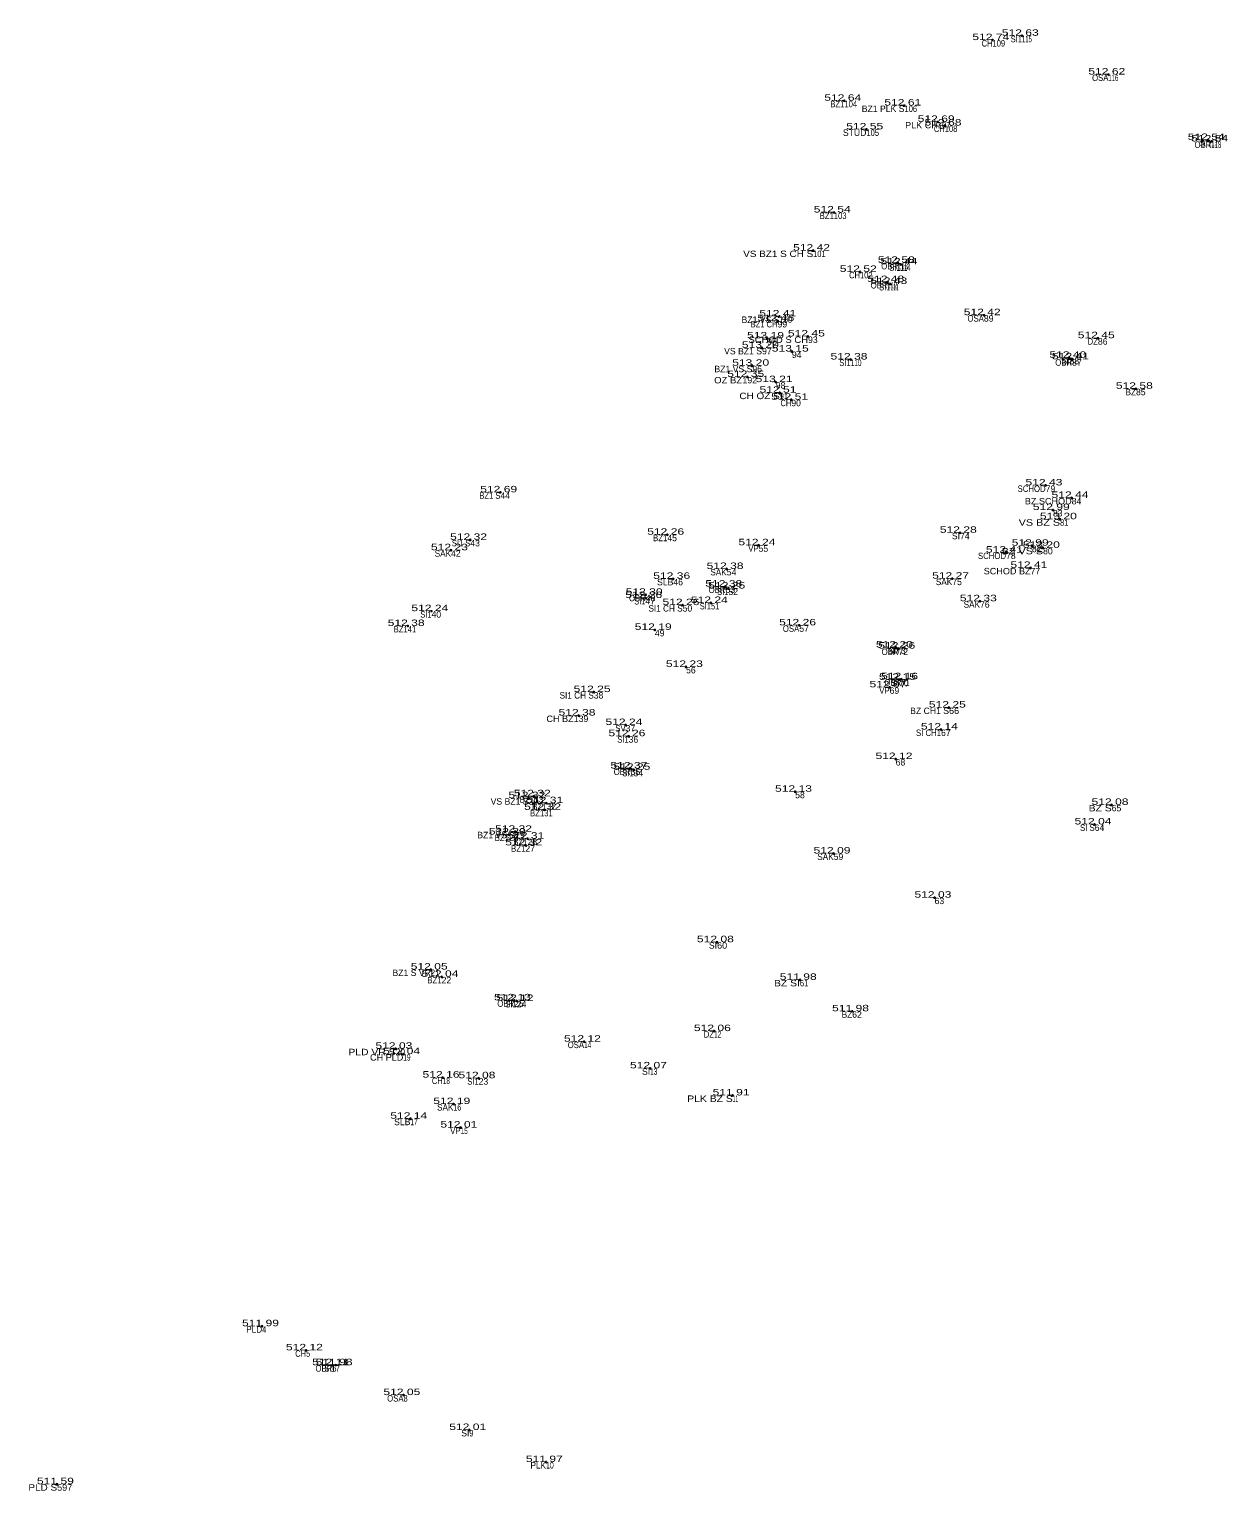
# Model space of a CAD drawing. Extents: x -643086 to -639283, y -1131805 to -1123269.
# Drawn here: x -639339.2 to -639283.5, y -1123337.4 to -1123269.5 of the extents above; entities that cross this region are included whole.
import ezdxf
from ezdxf.enums import TextEntityAlignment as Align

# ---------------------------------------------------------------- set-up
doc = ezdxf.new("R2010")
doc.units = 0
doc.header["$LTSCALE"] = 0.12
doc.header["$PDMODE"] = 32
doc.header["$PDSIZE"] = 0.06
for name, color, linetype in [('1', 7, 'Continuous'), ('2', 7, 'Continuous'), ('3', 7, 'Continuous'), ('4', 7, 'Continuous')]:
    doc.layers.add(name, color=color, linetype=linetype)

msp = doc.modelspace()

# ---------------------------------------------------------------- linework, layer by layer
at = {"layer": '1'}
for p in [(-639294.4, -1123269.99), (-639293.03, -1123269.79), (-639289.01, -1123271.59), (-639301.28, -1123272.81), (-639298.49, -1123273.03), (-639296.94, -1123273.79), (-639300.26, -1123274.14), (-639296.62, -1123273.96), (-639284.39, -1123274.63), (-639284.23, -1123274.7), (-639301.77, -1123278), (-639302.73, -1123279.77), (-639298.79, -1123280.34), (-639298.67, -1123280.41), (-639300.56, -1123280.76), (-639299.28, -1123281.23), (-639299.14, -1123281.32), (-639304.39, -1123283.04), (-639304.3, -1123282.83), (-639294.8, -1123282.77), (-639304.87, -1123283.85), (-639302.97, -1123283.76), (-639289.5, -1123283.84), (-639305.11, -1123284.29), (-639303.72, -1123284.46), (-639305.56, -1123285.12), (-639300.99, -1123284.83), (-639290.82, -1123284.75), (-639290.7, -1123284.82), (-639305.79, -1123285.64), (-639304.47, -1123285.88), (-639304.29, -1123286.37), (-639303.75, -1123286.7), (-639287.73, -1123286.19), (-639291.93, -1123290.68), (-639317.27, -1123291), (-639290.72, -1123291.26), (-639291.59, -1123291.82), (-639291.26, -1123292.25), (-639318.67, -1123293.21), (-639309.51, -1123292.97), (-639305.27, -1123293.46), (-639295.91, -1123292.88), (-639292.57, -1123293.48), (-639319.56, -1123293.69), (-639293.77, -1123293.8), (-639292.05, -1123293.58), (-639306.75, -1123294.56), (-639292.63, -1123294.51), (-639309.23, -1123295.02), (-639306.81, -1123295.38), (-639306.67, -1123295.47), (-639296.27, -1123295.01), (-639310.53, -1123295.91), (-639310.51, -1123295.76), (-639308.8, -1123296.24), (-639307.48, -1123296.14), (-639294.98, -1123296.06), (-639320.47, -1123296.52), (-639321.57, -1123297.21), (-639310.09, -1123297.39), (-639303.38, -1123297.18), (-639298.88, -1123298.21), (-639298.77, -1123298.26), (-639308.64, -1123299.11), (-639312.93, -1123300.28), (-639299.18, -1123300.06), (-639298.74, -1123299.71), (-639298.64, -1123299.68), (-639313.63, -1123301.37), (-639296.42, -1123301), (-639311.45, -1123301.81), (-639311.31, -1123302.33), (-639296.79, -1123302.02), (-639298.9, -1123303.39), (-639311.22, -1123303.83), (-639311.08, -1123303.89), (-639303.57, -1123304.91), (-639315.96, -1123305.21), (-639315.71, -1123305.12), (-639315.13, -1123305.44), (-639288.86, -1123305.52), (-639315.23, -1123305.75), (-639316.87, -1123306.9), (-639316.58, -1123306.77), (-639316.01, -1123307.09), (-639289.65, -1123306.43), (-639316.11, -1123307.4), (-639301.78, -1123307.78), (-639297.09, -1123309.83), (-639307.2, -1123311.9), (-639320.5, -1123313.17), (-639320, -1123313.51), (-639303.35, -1123313.65), (-639316.63, -1123314.6), (-639316.51, -1123314.63), (-639300.92, -1123315.11), (-639313.38, -1123316.52), (-639307.34, -1123316.03), (-639322.14, -1123316.85), (-639321.78, -1123317.1), (-639310.31, -1123317.76), (-639319.95, -1123318.19), (-639318.28, -1123318.22), (-639306.47, -1123319.02), (-639319.45, -1123319.42), (-639321.45, -1123320.1), (-639319.12, -1123320.51), (-639328.34, -1123329.74), (-639326.3, -1123330.86), (-639325.08, -1123331.55), (-639324.92, -1123331.55), (-639321.77, -1123332.94), (-639318.71, -1123334.56), (-639315.15, -1123336.05), (-639337.87, -1123337.08)]:
    msp.add_point(p, dxfattribs=at)

# ---------------------------------------------------------------- texts
at = {"layer": '2'}
for s, width, p in [('109', 0.85, (-639294.4, -1123270.29)), ('115', 0.55, (-639293.03, -1123270.09)), ('116', 0.55, (-639289.01, -1123271.89)), ('104', 0.85, (-639301.28, -1123273.11)), ('106', 0.85, (-639298.49, -1123273.33)), ('107', 0.85, (-639296.94, -1123274.09)), ('105', 0.85, (-639300.26, -1123274.44)), ('108', 0.85, (-639296.62, -1123274.26)), ('117', 0.55, (-639284.39, -1123274.93)), ('118', 0.55, (-639284.23, -1123275)), ('103', 0.85, (-639301.77, -1123278.3)), ('101', 0.75, (-639302.73, -1123280.07)), ('113', 0.55, (-639298.79, -1123280.64)), ('114', 0.55, (-639298.67, -1123280.71)), ('102', 0.85, (-639300.56, -1123281.06)), ('112', 0.55, (-639299.28, -1123281.53)), ('111', 0.45, (-639299.14, -1123281.62)), ('100', 0.85, (-639304.3, -1123283.13)), ('110', 0.6, (-639300.99, -1123285.13)), ('91', 0.8, (-639304.29, -1123286.67)), ('81', 0.8, (-639291.26, -1123292.55)), ('51', 0.8, (-639307.48, -1123296.44)), ('41', 0.8, (-639321.57, -1123297.51)), ('71', 0.8, (-639298.64, -1123299.98)), ('66', 1.05, (-639296.42, -1123301.3)), ('31', 0.8, (-639315.23, -1123306.05)), ('60', 1.05, (-639307.2, -1123312.2)), ('21', 0.8, (-639320.5, -1123313.47)), ('61', 0.85, (-639303.35, -1123313.95)), ('14', 0.6, (-639313.38, -1123316.82)), ('12', 0.6, (-639307.34, -1123316.33)), ('19', 0.6, (-639321.78, -1123317.4)), ('13', 0.6, (-639310.31, -1123318.06)), ('18', 0.6, (-639319.95, -1123318.49)), ('11', 0.45, (-639306.47, -1123319.32)), ('16', 0.65, (-639319.45, -1123319.72)), ('17', 0.6, (-639321.45, -1123320.4)), ('15', 0.6, (-639319.12, -1123320.81)), ('4', 0.75, (-639328.34, -1123330.04)), ('5', 0.75, (-639326.3, -1123331.16)), ('6', 0.85, (-639325.08, -1123331.85)), ('7', 0.75, (-639324.92, -1123331.85)), ('8', 0.75, (-639321.77, -1123333.24)), ('9', 0.75, (-639318.71, -1123334.86)), ('10', 0.65, (-639315.15, -1123336.35)), ('597', 1.05, (-639337.87, -1123337.38))]:
    msp.add_text(s, height=0.3, dxfattribs=dict(at, width=width)).set_placement(p)
for s, p in [('99', (-639304.39, -1123283.34)), ('89', (-639294.8, -1123283.07)), ('95', (-639304.87, -1123284.15)), ('93', (-639302.97, -1123284.06)), ('86', (-639289.5, -1123284.14)), ('97', (-639305.11, -1123284.59)), ('94', (-639303.72, -1123284.76)), ('96', (-639305.56, -1123285.42)), ('88', (-639290.82, -1123285.05)), ('87', (-639290.7, -1123285.12)), ('92', (-639305.79, -1123285.94)), ('98', (-639304.47, -1123286.18)), ('90', (-639303.75, -1123287)), ('85', (-639287.73, -1123286.49)), ('79', (-639291.93, -1123290.98)), ('44', (-639317.27, -1123291.3)), ('84', (-639290.72, -1123291.56)), ('83', (-639291.59, -1123292.12)), ('43', (-639318.67, -1123293.51)), ('45', (-639309.51, -1123293.27)), ('55', (-639305.27, -1123293.76)), ('74', (-639295.91, -1123293.18)), ('82', (-639292.57, -1123293.78)), ('42', (-639319.56, -1123293.99)), ('78', (-639293.77, -1123294.1)), ('80', (-639292.05, -1123293.88)), ('54', (-639306.75, -1123294.86)), ('77', (-639292.63, -1123294.81)), ('46', (-639309.23, -1123295.32)), ('53', (-639306.81, -1123295.68)), ('52', (-639306.67, -1123295.77)), ('75', (-639296.27, -1123295.31)), ('47', (-639310.53, -1123296.21)), ('48', (-639310.51, -1123296.06)), ('76', (-639294.98, -1123296.36)), ('40', (-639320.47, -1123296.82)), ('50', (-639308.8, -1123296.54)), ('49', (-639310.09, -1123297.69)), ('57', (-639303.38, -1123297.48)), ('73', (-639298.88, -1123298.51)), ('72', (-639298.77, -1123298.56)), ('56', (-639308.64, -1123299.41)), ('38', (-639312.93, -1123300.58)), ('69', (-639299.18, -1123300.36)), ('70', (-639298.74, -1123300.01)), ('39', (-639313.63, -1123301.67)), ('37', (-639311.45, -1123302.11)), ('67', (-639296.79, -1123302.32)), ('36', (-639311.31, -1123302.63)), ('68', (-639298.9, -1123303.69)), ('35', (-639311.22, -1123304.13)), ('34', (-639311.08, -1123304.19)), ('58', (-639303.57, -1123305.21)), ('30', (-639315.96, -1123305.51)), ('33', (-639315.71, -1123305.42)), ('32', (-639315.13, -1123305.74)), ('65', (-639288.86, -1123305.82)), ('26', (-639316.87, -1123307.2)), ('29', (-639316.58, -1123307.07)), ('64', (-639289.65, -1123306.73)), ('27', (-639316.11, -1123307.7)), ('28', (-639316.01, -1123307.39)), ('59', (-639301.78, -1123308.08)), ('63', (-639297.09, -1123310.13)), ('22', (-639320, -1123313.81)), ('25', (-639316.63, -1123314.9)), ('24', (-639316.51, -1123314.93)), ('62', (-639300.92, -1123315.41)), ('20', (-639322.14, -1123317.15)), ('23', (-639318.28, -1123318.52))]:
    msp.add_text(s, height=0.3, dxfattribs=at).set_placement(p)
at = {"layer": '3', "width": 1.4}
for s, p in [('512 74 ', (-639294.4, -1123269.99)), ('512 63 ', (-639293.03, -1123269.79)), ('512 62 ', (-639289.01, -1123271.59)), ('512 64 ', (-639301.28, -1123272.81)), ('512 61 ', (-639298.49, -1123273.03)), ('512 69 ', (-639296.94, -1123273.79)), ('512 68 ', (-639296.62, -1123273.96)), ('512 55 ', (-639300.26, -1123274.14)), ('512 54 ', (-639284.39, -1123274.63)), ('512 54 ', (-639284.23, -1123274.7)), ('512 54 ', (-639301.77, -1123278)), ('512 42 ', (-639302.73, -1123279.77)), ('512 52 ', (-639300.56, -1123280.76)), ('512 58 ', (-639298.79, -1123280.34)), ('512 44 ', (-639298.67, -1123280.41)), ('512 48 ', (-639299.28, -1123281.23)), ('512 43 ', (-639299.14, -1123281.32)), ('512 41 ', (-639304.3, -1123282.83)), ('512 42 ', (-639294.8, -1123282.77)), ('512 46 ', (-639304.39, -1123283.04)), ('513 20 ', (-639305.11, -1123284.29)), ('513 19 ', (-639304.87, -1123283.85)), ('512 45 ', (-639302.97, -1123283.76)), ('512 45 ', (-639289.5, -1123283.84)), ('513 15 ', (-639303.72, -1123284.46)), ('512 38 ', (-639300.99, -1123284.83)), ('512 40 ', (-639290.82, -1123284.75)), ('512 41 ', (-639290.7, -1123284.82)), ('512 35 ', (-639305.79, -1123285.64)), ('513 20 ', (-639305.56, -1123285.12)), ('513 21 ', (-639304.47, -1123285.88)), ('512 58 ', (-639287.73, -1123286.19)), ('512 51 ', (-639304.29, -1123286.37)), ('512 51 ', (-639303.75, -1123286.7)), ('512 69 ', (-639317.27, -1123291)), ('512 43 ', (-639291.93, -1123290.68)), ('512 44 ', (-639290.72, -1123291.26)), ('512 99 ', (-639291.59, -1123291.82)), ('513 20 ', (-639291.26, -1123292.25)), ('512 26 ', (-639309.51, -1123292.97)), ('512 28 ', (-639295.91, -1123292.88)), ('512 23 ', (-639319.56, -1123293.69)), ('512 32 ', (-639318.67, -1123293.21)), ('512 24 ', (-639305.27, -1123293.46)), ('512 41 ', (-639293.77, -1123293.8)), ('512 99 ', (-639292.57, -1123293.48)), ('513 20 ', (-639292.05, -1123293.58)), ('512 36 ', (-639309.23, -1123295.02)), ('512 38 ', (-639306.75, -1123294.56)), ('512 27 ', (-639296.27, -1123295.01)), ('512 41 ', (-639292.63, -1123294.51)), ('512 30 ', (-639310.51, -1123295.76)), ('512 38 ', (-639306.81, -1123295.38)), ('512 25 ', (-639306.67, -1123295.47)), ('512 26 ', (-639310.53, -1123295.91)), ('512 26 ', (-639308.8, -1123296.24)), ('512 24 ', (-639307.48, -1123296.14)), ('512 33 ', (-639294.98, -1123296.06)), ('512 24 ', (-639320.47, -1123296.52)), ('512 26 ', (-639303.38, -1123297.18)), ('512 38 ', (-639321.57, -1123297.21)), ('512 19 ', (-639310.09, -1123297.39)), ('512 20 ', (-639298.88, -1123298.21)), ('512 26 ', (-639298.77, -1123298.26)), ('512 23 ', (-639308.64, -1123299.11)), ('512 15 ', (-639298.74, -1123299.71)), ('512 16 ', (-639298.64, -1123299.68)), ('512 25 ', (-639312.93, -1123300.28)), ('512 07 ', (-639299.18, -1123300.06)), ('512 25 ', (-639296.42, -1123301)), ('512 38 ', (-639313.63, -1123301.37)), ('512 24 ', (-639311.45, -1123301.81)), ('512 26 ', (-639311.31, -1123302.33)), ('512 14 ', (-639296.79, -1123302.02)), ('512 37 ', (-639311.22, -1123303.83)), ('512 25 ', (-639311.08, -1123303.89)), ('512 12 ', (-639298.9, -1123303.39)), ('512 32 ', (-639315.96, -1123305.21)), ('512 32 ', (-639315.71, -1123305.12)), ('512 13 ', (-639303.57, -1123304.91)), ('512 32 ', (-639315.23, -1123305.75)), ('512 31 ', (-639315.13, -1123305.44)), ('512 08 ', (-639288.86, -1123305.52)), ('512 04 ', (-639289.65, -1123306.43)), ('512 30 ', (-639316.87, -1123306.9)), ('512 32 ', (-639316.58, -1123306.77)), ('512 31 ', (-639316.01, -1123307.09)), ('512 32 ', (-639316.11, -1123307.4)), ('512 09 ', (-639301.78, -1123307.78)), ('512 03 ', (-639297.09, -1123309.83)), ('512 08 ', (-639307.2, -1123311.9)), ('512 05 ', (-639320.5, -1123313.17)), ('512 04 ', (-639320, -1123313.51)), ('511 98 ', (-639303.35, -1123313.65)), ('512 13 ', (-639316.63, -1123314.6)), ('512 12 ', (-639316.51, -1123314.63)), ('511 98 ', (-639300.92, -1123315.11)), ('512 06 ', (-639307.34, -1123316.03)), ('512 03 ', (-639322.14, -1123316.85)), ('512 12 ', (-639313.38, -1123316.52)), ('512 04 ', (-639321.78, -1123317.1)), ('512 16 ', (-639319.95, -1123318.19)), ('512 08 ', (-639318.28, -1123318.22)), ('512 07 ', (-639310.31, -1123317.76)), ('512 19 ', (-639319.45, -1123319.42)), ('511 91 ', (-639306.47, -1123319.02)), ('512 14 ', (-639321.45, -1123320.1)), ('512 01 ', (-639319.12, -1123320.51)), ('511 99 ', (-639328.34, -1123329.74)), ('512 12 ', (-639326.3, -1123330.86)), ('512 11 ', (-639325.08, -1123331.55)), ('511 98 ', (-639324.92, -1123331.55)), ('512 05 ', (-639321.77, -1123332.94)), ('512 01 ', (-639318.71, -1123334.56)), ('511 97 ', (-639315.15, -1123336.05)), ('511 59 ', (-639337.87, -1123337.08))]:
    msp.add_text(s, height=0.3, dxfattribs=at).set_placement(p, align=Align.CENTER)
at = {"layer": '4'}
for s, width, p in [('CH', 0.8, (-639294.4, -1123270.29)), ('SI1', 0.8, (-639293.03, -1123270.09)), ('OSA', 0.9, (-639289.01, -1123271.89)), ('BZ1', 0.9, (-639301.28, -1123273.11)), ('PLK CH', 1.05, (-639296.94, -1123274.09)), ('CH', 0.8, (-639296.62, -1123274.26)), ('OBR', 0.9, (-639284.23, -1123275)), ('BZ1', 0.9, (-639301.77, -1123278.3)), ('VS BZ1 S CH S', 1.15, (-639302.73, -1123280.07)), ('OBR', 0.9, (-639298.79, -1123280.64)), ('SI1', 0.8, (-639298.67, -1123280.71)), ('CH', 0.8, (-639300.56, -1123281.06)), ('OBR', 0.9, (-639299.28, -1123281.53)), ('SI1', 0.8, (-639299.14, -1123281.62)), ('BZ1 CH', 0.85, (-639304.39, -1123283.34)), ('OSA', 0.9, (-639294.8, -1123283.07)), ('SCHOD S CH', 1.1, (-639302.97, -1123284.06)), ('DZ', 0.9, (-639289.5, -1123284.14)), ('SI1', 0.8, (-639300.99, -1123285.13)), ('OBR', 0.9, (-639290.7, -1123285.12)), ('OZ BZ1', 1.1, (-639305.79, -1123285.94)), ('CH OZ S', 1.15, (-639304.29, -1123286.67)), ('CH', 0.8, (-639303.75, -1123287)), ('BZ', 0.95, (-639287.73, -1123286.49)), ('SCHOD', 0.9, (-639291.93, -1123290.98)), ('BZ1 S', 0.85, (-639317.27, -1123291.3)), ('BZ SCHOD', 1.05, (-639290.72, -1123291.56)), ('VS BZ S', 1.25, (-639291.26, -1123292.55)), ('SI1 S', 0.8, (-639318.67, -1123293.51)), ('BZ1', 0.9, (-639309.51, -1123293.27)), ('VP', 0.9, (-639305.27, -1123293.76)), ('SAK', 0.95, (-639319.56, -1123293.99)), ('SCHOD', 0.9, (-639293.77, -1123294.1)), ('BZ VS S', 1.25, (-639292.05, -1123293.88)), ('SAK', 0.95, (-639306.75, -1123294.86)), ('SCHOD BZ', 1.05, (-639292.63, -1123294.81)), ('OBR', 0.9, (-639306.81, -1123295.68)), ('SI1', 0.8, (-639306.67, -1123295.77)), ('SAK', 0.95, (-639296.27, -1123295.31)), ('OBR', 0.9, (-639310.51, -1123296.06)), ('SI1', 0.8, (-639310.53, -1123296.21)), ('SI1', 0.8, (-639307.48, -1123296.44)), ('SAK', 0.95, (-639294.98, -1123296.36)), ('SI1', 0.8, (-639320.47, -1123296.82)), ('SI1 CH S', 0.95, (-639308.8, -1123296.54)), ('BZ1', 0.9, (-639321.57, -1123297.51)), ('OSA', 0.9, (-639303.38, -1123297.48)), ('OBR', 0.9, (-639298.77, -1123298.56)), ('SI1 CH S', 0.95, (-639312.93, -1123300.58)), ('VP', 0.9, (-639299.18, -1123300.36)), ('OBR', 0.9, (-639298.64, -1123299.98)), ('CH BZ1', 1.05, (-639313.63, -1123301.67)), ('SV', 0.9, (-639311.45, -1123302.11)), ('SI CH1', 0.9, (-639296.79, -1123302.32)), ('SI1', 0.8, (-639311.31, -1123302.63)), ('OBR', 0.9, (-639311.22, -1123304.13)), ('SI1', 0.8, (-639311.08, -1123304.19)), ('BZ1', 0.9, (-639315.71, -1123305.42)), ('BZ1', 0.9, (-639315.13, -1123305.74)), ('BZ S', 1.2, (-639288.86, -1123305.82)), ('BZ1', 0.9, (-639315.23, -1123306.05)), ('BZ1', 0.9, (-639316.87, -1123307.2)), ('SI S', 0.9, (-639289.65, -1123306.73)), ('BZ1', 0.9, (-639316.11, -1123307.7)), ('BZ1', 0.9, (-639316.01, -1123307.39)), ('SAK', 0.95, (-639301.78, -1123308.08)), ('BZ1', 0.9, (-639320, -1123313.81)), ('BZ SI', 1.2, (-639303.35, -1123313.95)), ('OBR', 0.9, (-639316.63, -1123314.9)), ('SI1', 0.8, (-639316.51, -1123314.93)), ('BZ', 0.95, (-639300.92, -1123315.41)), ('OSA', 0.9, (-639313.38, -1123316.82)), ('DZ', 0.9, (-639307.34, -1123316.33)), ('PLD VR S', 1.2, (-639322.14, -1123317.15)), ('CH PLD', 1.05, (-639321.78, -1123317.4)), ('CH', 0.8, (-639319.95, -1123318.49)), ('SI1', 0.8, (-639318.28, -1123318.52)), ('PLK BZ S', 1.2, (-639306.47, -1123319.32)), ('SAK', 0.95, (-639319.45, -1123319.72)), ('VP', 0.9, (-639319.12, -1123320.81)), ('PLD', 0.95, (-639328.34, -1123330.04)), ('CH', 0.8, (-639326.3, -1123331.16)), ('OBR', 0.9, (-639325.08, -1123331.85)), ('SI1', 0.8, (-639324.92, -1123331.85)), ('OSA', 0.9, (-639321.77, -1123333.24)), ('PLK', 0.95, (-639315.15, -1123336.35)), ('PLD S', 1.15, (-639337.87, -1123337.38))]:
    msp.add_text(s, height=0.3, dxfattribs=dict(at, width=width)).set_placement(p, align=Align.RIGHT)
for s, p in [('BZ1 PLK S', (-639298.49, -1123273.33)), ('STUD', (-639300.26, -1123274.44)), ('SI', (-639284.39, -1123274.93)), ('BZ1 VS S', (-639304.3, -1123283.13)), ('VS BZ1 S', (-639305.11, -1123284.59)), ('BZ1 VS S', (-639305.56, -1123285.42)), ('SI', (-639290.82, -1123285.05)), ('SI', (-639295.91, -1123293.18)), ('SLB', (-639309.23, -1123295.32)), ('SI', (-639298.88, -1123298.51)), ('SI', (-639298.74, -1123300.01)), ('BZ CH1 S', (-639296.42, -1123301.3)), ('VS BZ1 S', (-639315.96, -1123305.51)), ('BZ1 VS S', (-639316.58, -1123307.07)), ('SI', (-639307.2, -1123312.2)), ('BZ1 S VR', (-639320.5, -1123313.47)), ('SI', (-639310.31, -1123318.06)), ('SLB', (-639321.45, -1123320.4)), ('SI', (-639318.71, -1123334.86))]:
    msp.add_text(s, height=0.3, dxfattribs=at).set_placement(p, align=Align.RIGHT)

doc.saveas('drawing.dxf')
